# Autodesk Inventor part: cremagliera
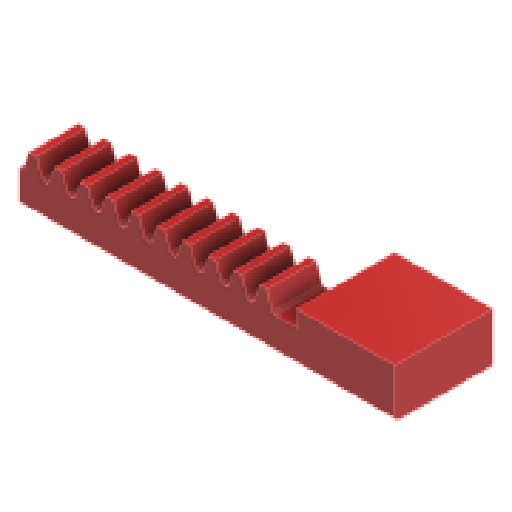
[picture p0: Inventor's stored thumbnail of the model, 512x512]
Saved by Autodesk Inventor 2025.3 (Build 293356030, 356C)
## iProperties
Created: 2026-01
Part Number: cremagliera
Material: Plastica ABS
Document SubType Name: Modeling
Designer: 18907419
Density: 1.06 g/cm^3
Appearance: Rosso
Author: 18907419
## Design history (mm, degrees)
sketch "Schizzo1"
  geometry: L1 (0, 0)-(34, 0); L2 (34, 0)-(34, 4); L3 (34, 4)-(0, 4); L4 (0, 4)-(0, 0); 1 further point
  constraints: 8 end point, 3 perpendicular, 1 coincident
  dimensions: "d0" = 34 distance of L3.end L2.end; "d1" = 4 distance of L2.end L1.end
extrude "Estrusione1" new body sketch "Schizzo1" distance "d2" = 6; taper "d3" = 0 deg
sketch "Schizzo2"
  geometry: L1 (1.64, 4)-(1.64, 6.25); L2 (1.64, 6.25)-(1.219, 6.25); L3 (1.219, 6.25)-(0.4, 4); L4 (0.4, 4)-(1.64, 4); L5 (34, 4)-(0, 4) reference; L6 (0.855, 5.25)-(1.64, 5.25); L7 (1.64, 6.25)-(2.061, 6.25); L8 (2.061, 6.25)-(2.88, 4); L9 (2.88, 4)-(1.64, 4); L10 (2.425, 5.25)-(1.64, 5.25); L11 (0, 4)-(0, 0) reference; 1 further point
  constraints: 18 end point, 5 point on line, 3 symmetric about line, 2 perpendicular
  dimensions: "d4" = 70 deg angle of L4 L3; "d6" = 1.25 distance between parallel lines of L4 L6; "d7" = 0.785 distance of L6.start L6.end; "d8" = 2.25 distance of L1.start L1.end; "d15" = 0.4 distance from line of L11 L3.end
extrude "Estrusione2" join sketch "Schizzo2" stored distance "d9" = 10; taper "d10" = 0 deg
fillet "Raccordo1" dims "d11" = 0.38
pattern_linear "Serie rettangolare1" dims "d14" = 3.14
sketch "Schizzo3"
  geometry: L1 (34, 4)-(3.146, 4) reference; L2 (38.046, 5.25)-(0.059, 5.25); L3 (0, 4)-(34, 4); 1 further point
  constraints: 4 end point, 1 collinear, 1 parallel
  dimensions: "d48" = 1.25 distance from line of L3.start L2
feature "SupEstrusione1" sketch "Schizzo3" dims "d18" = 10, "d19" = 0
sketch "Schizzo42"
  geometry: L1 (0, 0)-(-6, 0) reference; L2 (-6, 0)-(6, 0); L3 (6, 0)-(6, 6); L4 (6, 6)-(-6, 6); L5 (-6, 6)-(-6, 0); 2 further points
  constraints: 8 end point, 2 parallel, 1 horizontal, 1 perpendicular
  dimensions: "d254" = 12 distance of L4.end L3.end; "d255" = 6 distance of L3.end L2.end
extrude "Estrusione34" join sketch "Schizzo42" distance "d256" = 12; taper "d257" = 0 deg
chamfer "Smusso24" distance "d258" = 0.4; stored, may be unused: second distance "d259" = 2, angle "d260" = 45 deg
node "Solido1"
node "Superf1"
